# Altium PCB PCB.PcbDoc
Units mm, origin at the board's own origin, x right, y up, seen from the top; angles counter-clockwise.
Board outline 42.42 x 60.96 mm, 2 copper layers (Top Layer, Bottom Layer); 65 components, 46 nets, 264 pads, 71 vias.
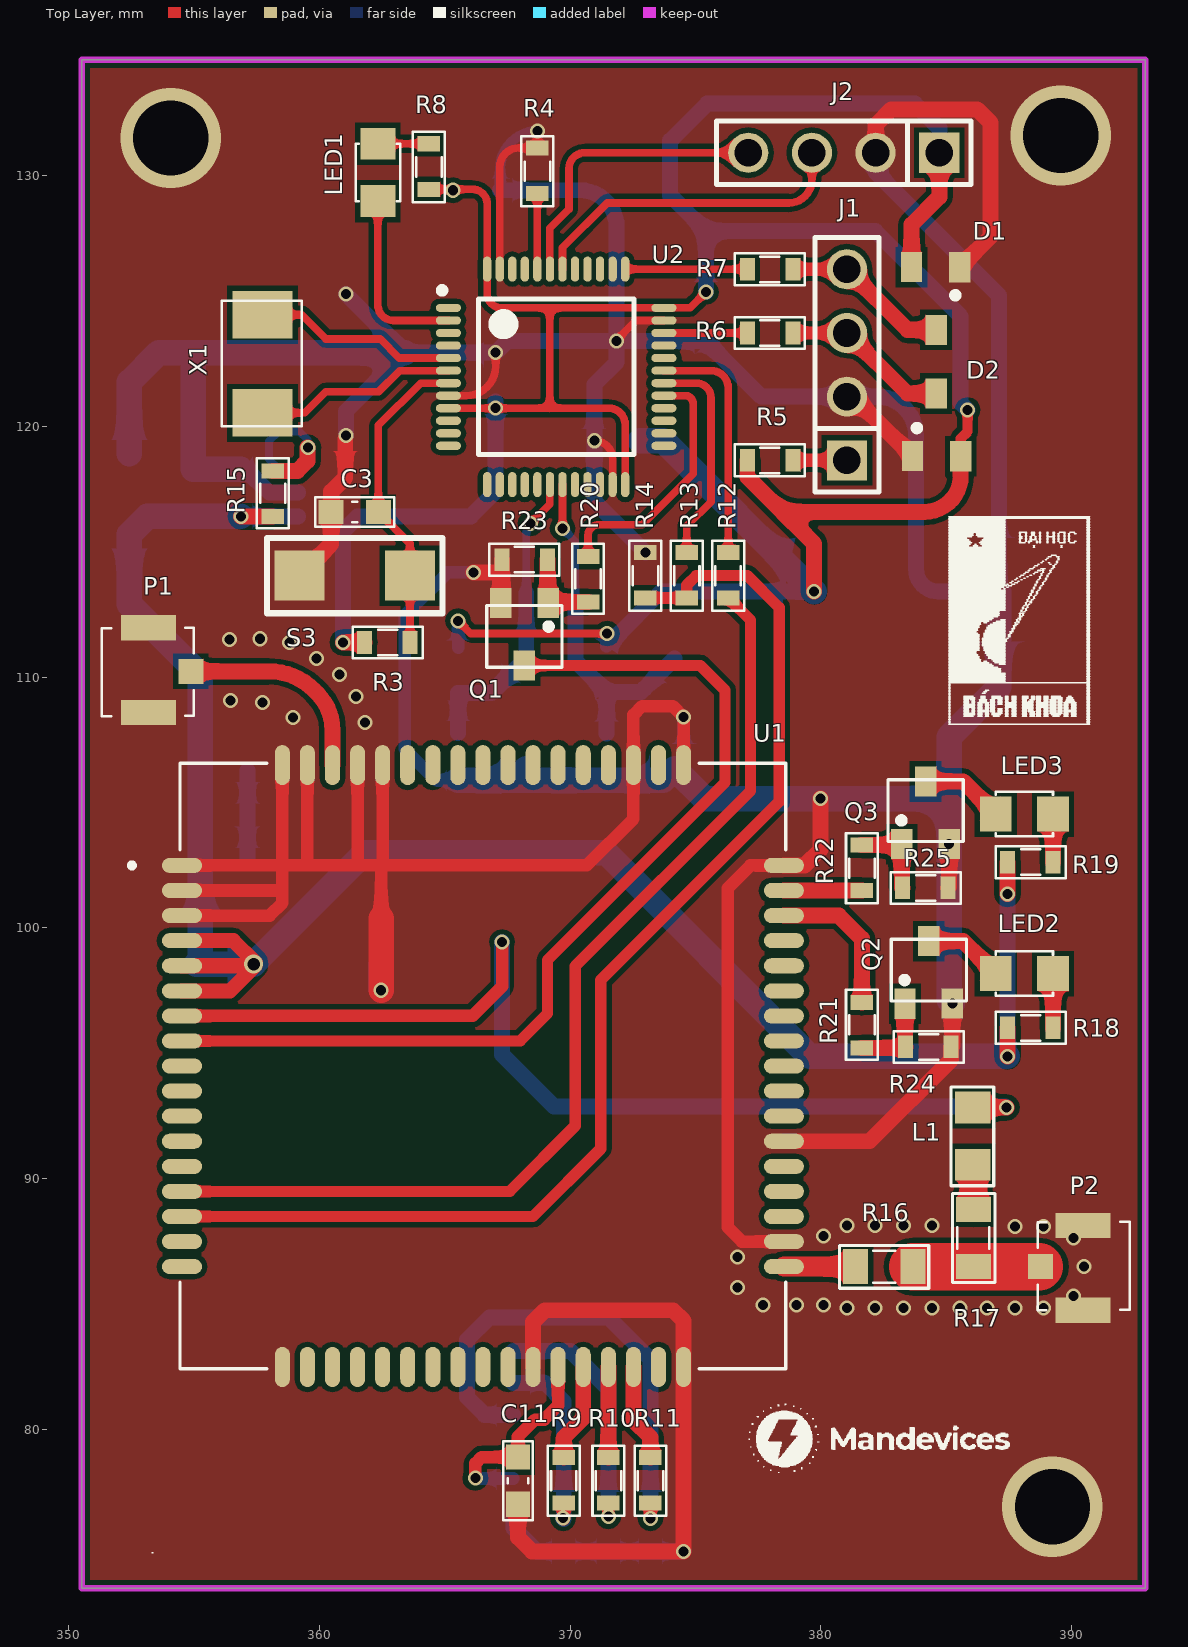
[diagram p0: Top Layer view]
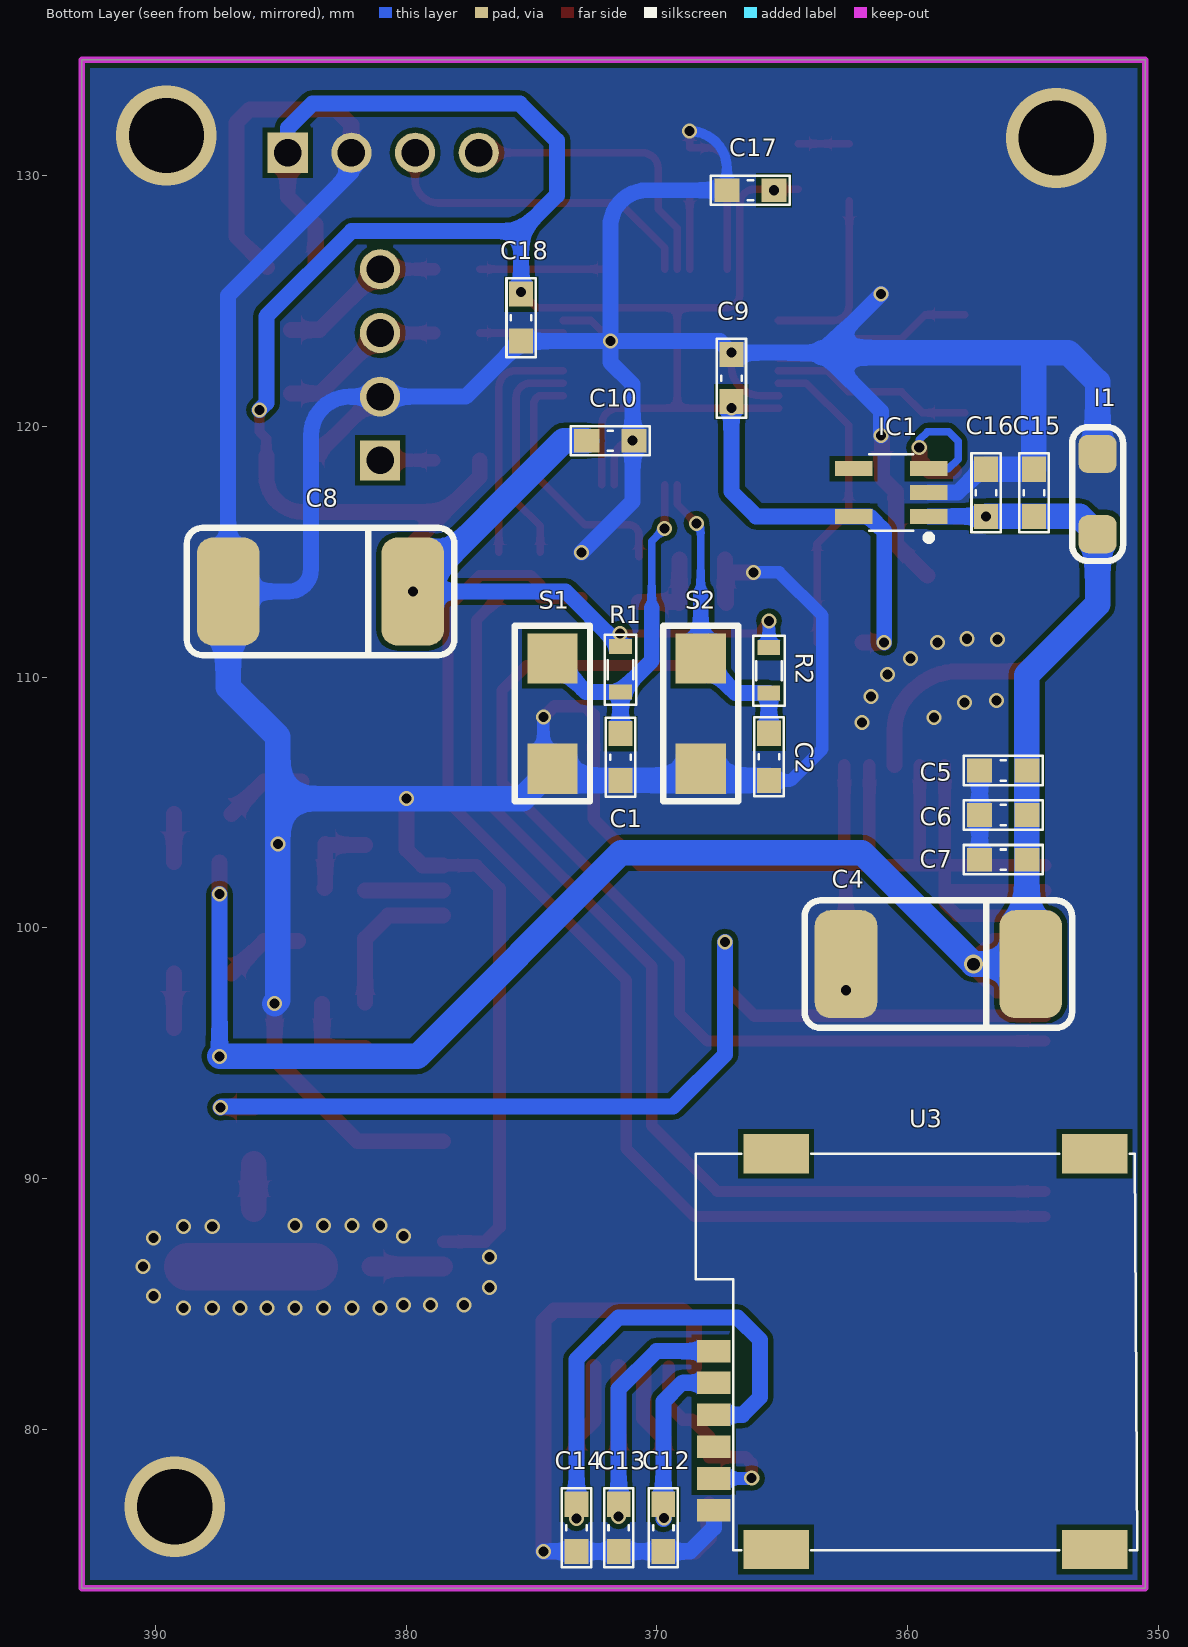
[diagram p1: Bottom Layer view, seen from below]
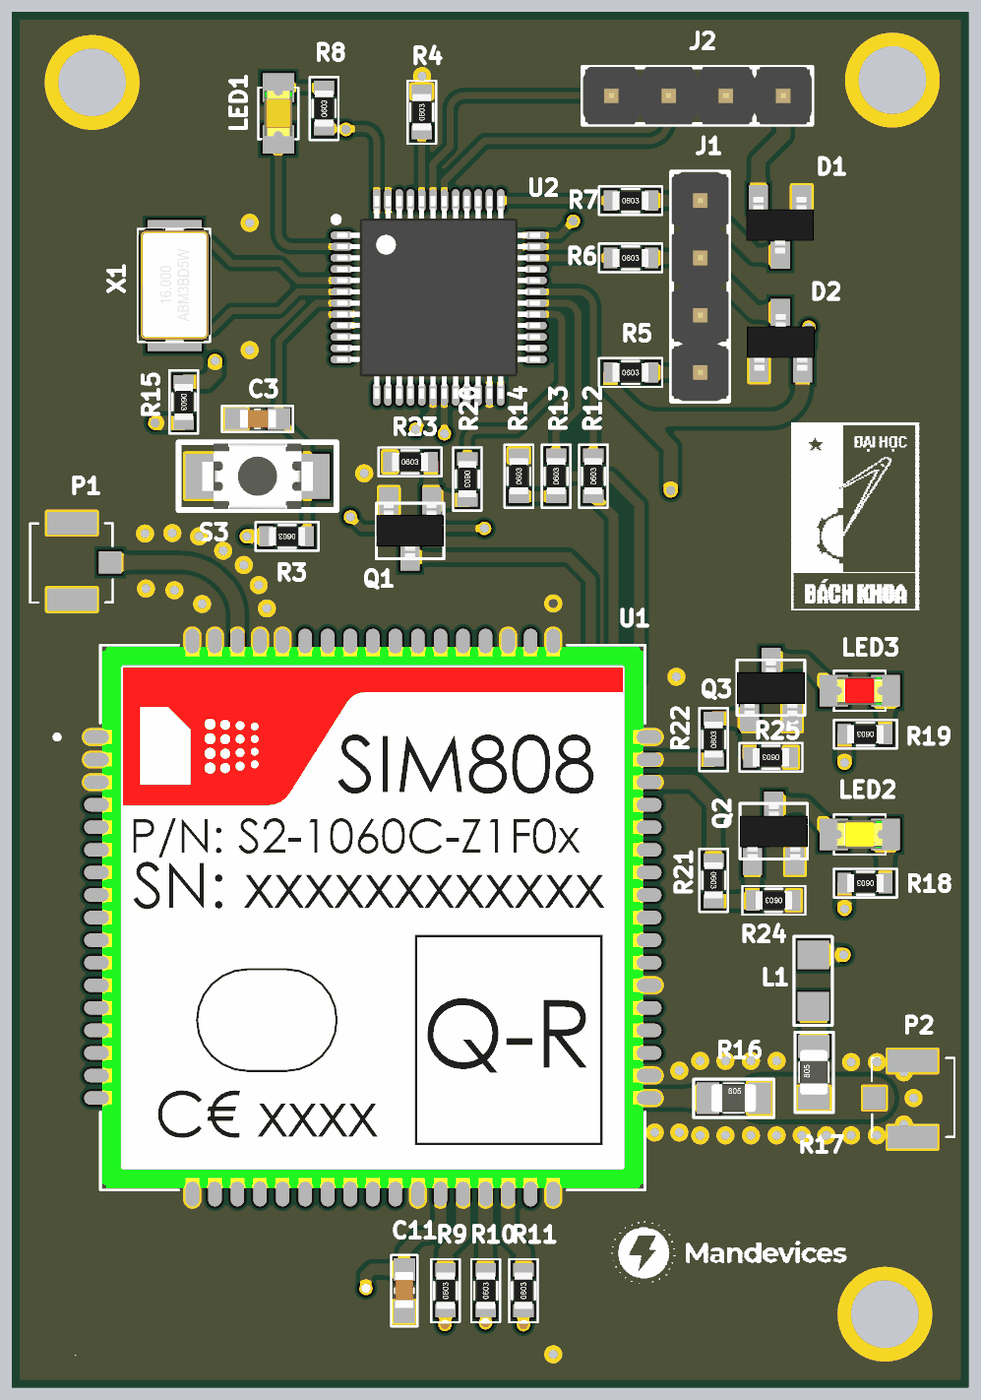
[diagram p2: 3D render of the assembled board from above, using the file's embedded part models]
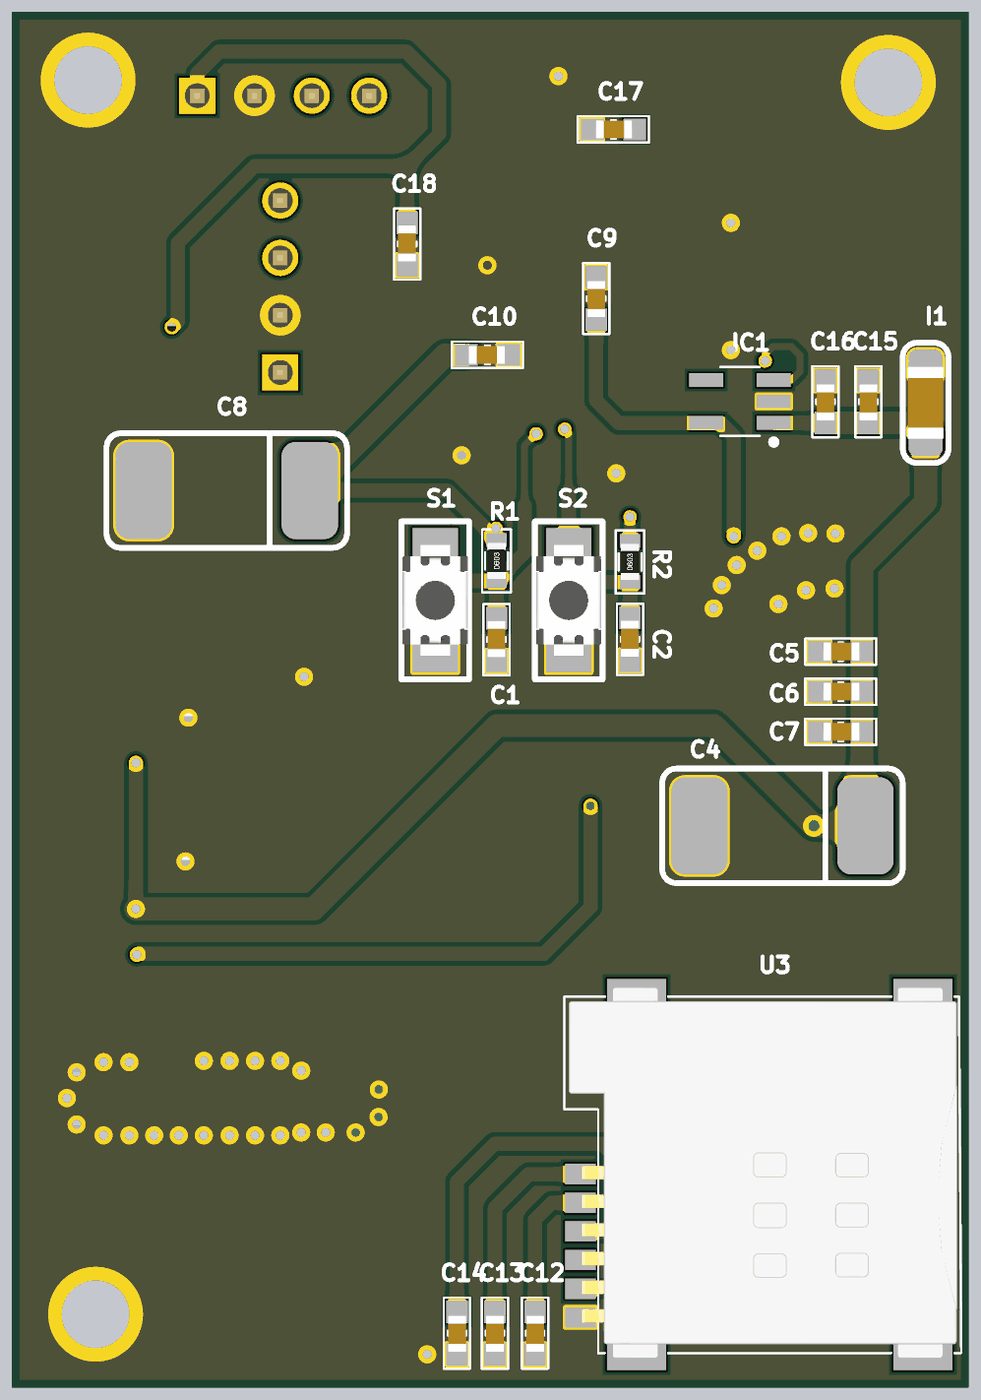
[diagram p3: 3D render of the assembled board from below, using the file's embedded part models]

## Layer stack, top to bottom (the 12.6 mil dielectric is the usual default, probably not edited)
Top Solder: solder mask 0.0102, Solder Resist, Dk 3.5
Top Layer: signal copper 0.0356
Dielectric 1: dielectric 0.32, FR-4, Dk 4.8
Bottom Layer: signal copper 0.0356
Bottom Solder: solder mask 0.0102, Solder Resist, Dk 3.5

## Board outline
350.52,73.66 392.938,73.66 392.938,134.62 350.52,134.62

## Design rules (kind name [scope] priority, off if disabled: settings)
Clearance [All] p1: gap=0.254 ignorepadtopadclearanceinfootprint=TRUE except(0.1: Arc-Arc Arc-Track Arc-SMDPad Track-Track Track-SMDPad SMDPad-SMDPad; 0.2: Arc-Fill Arc-Poly Arc-Region Track-Fill Track-Poly Track-Region SMDPad-Fill SMDPad-Poly SMDPad-Region THPad-Fill THPad-Poly THPad-Region Via-Fill Via-Poly Via-Region Fill-Fill Fill-Poly Fill-Region Poly-Poly Poly-Region Region-Region)
PolygonConnect [All] p1: connectstyle=Direct reliefconductorwidth=0.254 reliefentries=4 polygonreliefangle="90 Angle" airgapwidth=0.254
RoutingVias [All] p1: holewidth=0.4 width=0.6 viastyle="Through Hole" minholewidth=0.4 minwidth=0.6 maxholewidth=0.4 maxwidth=0.6
SolderMaskExpansion [All] p1: expansion=0.102
Width [All] p1: maxlimit=2.032 minlimit=0.305 preferedwidth=0.5
30 further rules are at their usual default settings.

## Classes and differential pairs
component class Sheet1: C3 C4 C5 C6 C7 C8 C9 C10 C11 C12 C13 C14 C15 C16 C17 C18 D1 D2 I1 IC1 J1 J2 L1 LED1 LED2 LED3 P1 P2 Q1 Q2 Q3 R3 R4 R5 R6 R7 R8 R9 R10 R11 R12 R13 R14 R15 R16 R17 R18 R19 R20 R21 R22 R23 R24 R25 S2 S3 U1 U2 U3 X1

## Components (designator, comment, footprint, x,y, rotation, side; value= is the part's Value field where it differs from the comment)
C1 "10uF" CAP_0603 371.45,106.807 r90 bottom value=33p
C2 "10uF" CAP_0603 365.531,106.82 r90 bottom value=33p
C3 "10uF" CAP_0603 361.411,116.586 r0 top value=33p
C4 "100uF" CAP_7343 358.902,98.552 r0 bottom
C5 "10uF" CAP_0603 356.188,106.274 r180 bottom value=33p
C6 "100nF" CAP_0603 356.188,104.496 r180 bottom value=33p
C7 "33pF" CAP_0603 356.188,102.718 r180 bottom value=33p
C8 "100uF" CAP_7343 383.54,113.411 r0 bottom
C9 "10uF" CAP_0603 367.03,121.92 r270 bottom value=33p
C10 "100nF" CAP_0603 371.856,119.424 r0 bottom value=33p
C11 "100nF" CAP_0603 367.919,77.953 r90 top value=33p
C12 "22pF" CAP_0603 369.744,76.073 r270 bottom value=33p
C13 "22pF" CAP_0603 371.522,76.073 r270 bottom value=33p
C14 "22pF" CAP_0603 373.204,76.073 r270 bottom value=33p
C15 "10uF" CAP_0603 354.965,117.348 r270 bottom value=33p
C16 "100nF" CAP_0603 356.87,117.348 r270 bottom value=33p
C17 "10uF" CAP_0603 366.268,129.413 r180 bottom value=33p
C18 "100nF" CAP_0603 375.412,124.333 r90 bottom value=33p
D1 "DIODE-BAV99" SOT23 384.599,125.097 r180 top
D2 "DIODE-BAV99" SOT23 384.589,120.057 r0 top
I1 "Batt" CAP_3216 352.425,117.297 r270 bottom value=33p
IC1 "RT9013" SOT23-5 360.656,117.358 r0 bottom
J1 "ST_LINK" JP4-D1T 381.038,118.641 r90 top
J2 "MPU" JP4-D1T 384.721,130.909 r180 top
L1 "47nH" L-0805 386.055,91.694 r270 top value="150 mH"
LED1 "LED" LED-0805-Orange 362.331,131.267 r270 top value="LED 3 ly Single Colour"
LED2 "LED" LED-0805-Yellow 389.255,98.171 r180 top value="LED 3 ly Single Colour"
LED3 "LED" LED-0805-Red 389.255,104.536 r180 top value="LED 3 ly Single Colour"
P1 "Antenna" IPXS 354.457,110.236 r0 top
P2 "Antenna" IPXS 389.179,86.479 r180 top
Q1 "2SC1815" SOT23D 368.173,111.709 r180 top value=C1815
Q2 "2SC1815" SOT23D 384.302,98.222 r0 top value=C1815
Q3 "2SC1815" SOT23D 384.175,104.587 r0 top value=C1815
R1 "10k" RES-SMD-0603 371.45,110.297 r90 bottom
R2 "10k" RES-SMD-0603 365.531,110.249 r90 bottom
R3 "10k" RES-SMD-0603 362.722,111.379 r180 top
R4 "100k" RES-SMD-0603 368.693,130.175 r90 top
R5 "10R" RES-SMD-0603 377.952,118.641 r0 top
R6 "10R" RES-SMD-0603 377.952,123.721 r0 top
R7 "10R" RES-SMD-0603 377.952,126.261 r0 top
R8 "1k" RES-SMD-0603 364.363,130.34 r90 top
R9 "22R" RES-SMD-0603 369.744,77.953 r90 top
R10 "22R" RES-SMD-0603 371.526,77.953 r90 top
R11 "22R" RES-SMD-0603 373.202,77.953 r90 top
R12 "1k" RES-SMD-0603 376.301,114.046 r90 top
R13 "1k" RES-SMD-0603 374.65,114.046 r90 top
R14 "4.7k" RES-SMD-0603 372.999,114.046 r90 top
R15 "100k" RES-SMD-0603 358.14,117.335 r270 top
R16 "0R" RES-SMD-0805 382.524,86.489 r0 top
R17 "10R" RES-SMD-0805 386.08,87.632 r90 top
R18 "1k" RES-SMD-0603 388.366,96.012 r180 top
R19 "1k" RES-SMD-0603 388.366,102.616 r180 top
R20 "4.7k" RES-SMD-0603 370.713,113.919 r270 top
R21 "4.7k" RES-SMD-0603 381.635,96.139 r270 top
R22 "4.7k" RES-SMD-0603 381.635,102.377 r90 top
R23 "47k" RES-SMD-0603 368.173,114.681 r0 top
R24 "47k" RES-SMD-0603 384.302,95.25 r180 top
R25 "47k" RES-SMD-0603 384.175,101.59 r180 top
S1 "SW-SMD" "SW 3x2x4" 374.167,108.544 r90 bottom
S2 "SW-SMD" "SW 3x2x4" 368.249,108.544 r90 bottom
S3 "SW-SMD" "SW 3x2x4" 361.411,114.046 r0 top
U1 "SIM808" XCVR_SIM808 366.522,94.488 r0 top
U2 "STM32" "LQFP 48" 369.443,121.971 r0 top
U3 "SIM-KF016" "Sim Socket" 360.045,83.185 r90 bottom value="Sim holder"
X1 "8Mhz" "XTAL 5032 SMD" 357.728,122.517 r90 top value=4Mhz

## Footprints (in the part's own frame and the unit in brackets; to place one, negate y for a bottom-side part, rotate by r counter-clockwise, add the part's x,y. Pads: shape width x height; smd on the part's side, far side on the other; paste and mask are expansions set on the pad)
CAP_0603 [mm]
  rect 1x0.95 smd mask+0.076: 1(-0.94,0) 2(0.94,0)
  silkscreen extent -1.57,-0.58 1.57,0.58, body extent -0.77,-0.39 0.83,0.41, height 0.9
CAP_3216 [mil]
  rrect50% 60x60 smd: 1(-62.99,0) 2(62.99,0)
  silkscreen extent -105,-40 105,40, body extent -63,-31 63,31, height 39
CAP_7343 [mm] "Capacitor Tantalum 7343"
  rrect50% 2.5x4.3 smd: 1(-3.81,0) 2(3.556,0)
  silkscreen extent -5.46,-2.54 5.21,2.54, body extent -3.81,-2.29 3.56,2.29, height 3
IPXS [mm] "SOT 23 _ 1-3-2"
  rect 1x1 smd: 1(0.415,-0.01)
  rect 2.2x1 smd: 2(-1.273,-1.658) 3(-1.278,1.73)
  silkscreen extent -3.13,-1.79 0.53,1.73, body extent -2.83,-1.49 0.31,1.56, height 1.55
JP4-D1T [mm] "4 pins, 1 row, straight, gold plating"
  rect 1.6x1.6 hole 1.1: 1(0,0)
  round 1.6 hole 1.1: 2(2.54,0) 3(5.08,0) 4(7.62,0)
  silkscreen extent -1.27,-1.27 8.89,1.27, body extent -1.27,-1.27 8.89,1.27, height 8.54
L-0805 [mil] "Compoment SMD 80x50mil"
  rect 50x55 smd: 1(-45,0) 2(45,0)
  silkscreen extent -77,-34 78,33, body extent -50,-20 50,20, height 43
LED-0805-Orange [mil]
  rect 50x55 smd: 1(0,0) 2(90,0)
  silkscreen extent 0,-35 90,35, body extent 5,-25 85,25, height 43
LED-0805-Red [mil]
  rect 50x55 smd: 1(0,0) 2(90,0)
  silkscreen extent 0,-35 90,35, body extent 5,-25 85,25, height 43
LED-0805-Yellow [mil]
  rect 50x55 smd: 1(0,0) 2(90,0)
  silkscreen extent 0,-35 90,35, body extent 5,-25 85,25, height 43
"LQFP 48" [mm] "LQFP, 48-Leads, Body 7,00x7,00mm, Pitch 0,50mm, IPC Medium Density"
  oval 1x0.33 smd: 1(-4.296,2.75) 2(-4.296,2.25) 3(-4.296,1.75) 4(-4.296,1.25) 5(-4.296,0.75) 6(-4.296,0.25) 7(-4.296,-0.25) 8(-4.296,-0.75) 9(-4.296,-1.25) 10(-4.296,-1.75) 11(-4.296,-2.25) 12(-4.296,-2.75) 25(4.296,-2.75) 26(4.296,-2.25) 27(4.296,-1.75) 28(4.296,-1.25) 29(4.296,-0.75) 30(4.296,-0.25) 31(4.296,0.25) 32(4.296,0.75) 33(4.296,1.25) 34(4.296,1.75) 35(4.296,2.25) 36(4.296,2.75)
  oval 0.33x1 smd: 13(-2.75,-4.296) 14(-2.25,-4.296) 15(-1.75,-4.296) 16(-1.25,-4.296) 17(-0.75,-4.296) 18(-0.25,-4.296) 19(0.25,-4.296) 20(0.75,-4.296) 21(1.25,-4.296) 22(1.75,-4.296) 23(2.25,-4.296) 24(2.75,-4.296) 37(2.75,4.296) 38(2.25,4.296) 39(1.75,4.296) 40(1.25,4.296) 41(0.75,4.296) 42(0.25,4.296) 43(-0.25,4.296) 44(-0.75,4.296) 45(-1.25,4.296) 46(-1.75,4.296) 47(-2.25,4.296) 48(-2.75,4.296)
  silkscreen extent -4.67,-3.1 3.1,3.57, body extent -4.5,-4.5 4.5,4.5, height 1.6
RES-SMD-0603 [mm]
  rect 0.6x0.9 smd: 1(-0.889,0) 2(0.927,0)
  silkscreen extent -1.4,-0.64 1.4,0.64, body extent -0.8,-0.4 0.8,0.4, height 0.43
RES-SMD-0805 [mil]
  rect 39.37x55 smd: 1(-45,0) 2(45,0)
  silkscreen extent -70,-34 70,33, body extent -39,-25 39,25, height 31
"Sim Socket" [mm] "Socket Micro Sim 6P Push"
  rect 0.9x1.35 smd: 1(-5.145,7.685) 2(-2.605,7.685) 3(-0.065,7.685) 5(-6.415,7.685) 6(-3.875,7.685) 7(-1.335,7.685)
  rect 1.56x2.61 smd: ""(-7.975,-7.5) ""(-7.975,5.2) ""(7.805,-7.5) ""(7.805,5.2)
  silkscreen extent -8,-9.2 7.8,8.4, body extent -8.2,-9 8.2,8.2, height 1.35
SOT23 [mm] "SOT 23 _ 1-3-2"
  rect 0.85x1.2 smd: 1(-0.94,-1.245) 2(0.985,-1.25) 3(0.005,1.25)
  silkscreen extent -0.89,-0.25 -0.64,0, body extent -1.47,-1.33 1.53,1.17, height 1.06
SOT23-5 [mm] "SOT23, 5-Leads, Body 3.0x3.0mm (max), Pitch 0.95mm, IPC Medium Density"
  rect 1.5x0.6 smd: 1(-1.5,0.95) 2(-1.5,0) 3(-1.5,-0.95) 4(1.5,-0.95) 5(1.5,0.95)
  silkscreen extent -1.62,-1.52 0.87,1.92, body extent -1.75,-1.52 1.75,1.53, height 1.45
SOT23D [mm] "SOT 23C - 1-3-2 - BCE"
  rect 0.85x1.2 smd: 1(-0.95,-1.25) 2(0.94,-1.245) 3(0,1.25)
  silkscreen extent -1.5,-1.14 1.5,1.32, body extent -1.5,-1.17 1.5,1.33, height 1.06
"SW 3x2x4" [mm]
  rect 2x2 smd: 1(-2.2,0) 2(2.2,0)
  silkscreen extent -3.5,-1.5 3.5,1.5, body extent -2.45,-1.45 2.45,1.45, height 2
XCVR_SIM808 [mm]
  oval 1.6x0.6 smd: 1(-12,8) 2(-12,7) 3(-12,6) 4(-12,5) 5(-12,4) 6(-12,3) 7(-12,2) 8(-12,1) 9(-12,0) 10(-12,-1) 11(-12,-2) 12(-12,-3) 13(-12,-4) 14(-12,-5) 15(-12,-6) 16(-12,-7) 17(-12,-8) 35(12,-8) 36(12,-7) 37(12,-6) 38(12,-5) 39(12,-4) 40(12,-3) 41(12,-2) 42(12,-1) 43(12,0) 44(12,1) 45(12,2) 46(12,3) 47(12,4) 48(12,5) 49(12,6) 50(12,7) 51(12,8)
  oval 0.6x1.6 smd: 18(-8,-12) 19(-7,-12) 20(-6,-12) 21(-5,-12) 22(-4,-12) 23(-3,-12) 24(-2,-12) 25(-1,-12) 26(0,-12) 27(1,-12) 28(2,-12) 29(3,-12) 30(4,-12) 31(5,-12) 32(6,-12) 33(7,-12) 34(8,-12) 52(8,12) 53(7,12) 54(6,12) 55(5,12) 56(4,12) 57(3,12) 58(2,12) 59(1,12) 60(0,12) 61(-1,12) 62(-2,12) 63(-3,12) 64(-4,12) 65(-5,12) 66(-6,12) 67(-7,12) 68(-8,12)
  silkscreen extent -14.1,-12.07 12.07,12.07, body extent -12,-12 12,12, height 2.8
"XTAL 5032 SMD" [mm] "SMD 5032 XTAL Footprint"
  rect 1.9x2.4 smd: 1(-1.981,0) 2(1.93,0)
  silkscreen extent -2.51,-1.57 2.49,1.63, body extent -2.5,-1.6 2.5,1.6, height 1.31

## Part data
C1 C2 C3 C5 C6 C7 C9 C10 C11 C12 C13 C14 C15 C16 C17 C18: library part CapSMD, "Capacitor"
C4 C8: library part "Cap Pol", "Tantalum"
D1 D2: "ZENER, SOT23,", Current - Average Rectified (Io) (per Diode)=200mA, Current - Reverse Leakage @ Vr="2.5礎 @ 70V", Manufacturer="ON Semiconductor / Fairchild", Manufacturer Part Number=BAV99, Package / Case="TO-236-3, SC-59, SOT-23-3", Standard Package=1, Supplier Device Package="SOT-23-3 (TO-236)", Supplier Part Number 1=BAV99FSCT-ND, Voltage - DC Reverse (Vr) (Max)=70V, Voltage - Forward (Vf) (Max) @ If="1.25V @ 150mA"
I1: library part CapSMD, "Pad"
IC1: "RT9013-33GB IC REG LINEAR 3.3V 500mA SOT23-5"
J1 J2: library part Header4, "Header IDC, 4 x 1 Pin Vertical 2.54mm Pitch (Non-Boxed, Male)", Manufacturer="Würth Elektronik eiSos GmbH", partNo=613002143121
L1: library part "Inductor Ferit", "Inductor"
LED1 LED2 LED3: "LED Single colour Green and Red"
P1 P2: library part IPXSx66, "Antenna GSM GPS"
Q1 Q2 Q3: "NPN 600mW, ECB"
R1 R2 R3 R4 R5 R6 R7 R8 R9 R10 R11 R12 R13 R14 R15 R16 R17 R18 R19 R20 R21 R22 R23 R24 R25: library part "Resistor - SMD", "Resistor", Manufacturer="Generic Components"
S1 S2 S3: "Switch"
U1: "SIM808 GPS, GPRS/GSM RF Arduino Platform Evaluation Expansion Board", Package=None
U2: library part STM32F103C8T6, "STM32 ARM-based 32-bit MCU with 64 Kbytes Flash, 64-pin LQFP, Industrial Temperature"
U3: library part "Sim holder", "SIM Card Holder KF-016"
X1: library part XT2, "Crystal For all Crystal 2pin."

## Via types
v1: diameter 0.6, hole 0.4, Top Layer to Bottom Layer, 67 vias
v2: diameter 4, hole 3, Top Layer to Bottom Layer, 3 vias
v3: diameter 0.762, hole 0.508, Top Layer to Bottom Layer, 1 vias

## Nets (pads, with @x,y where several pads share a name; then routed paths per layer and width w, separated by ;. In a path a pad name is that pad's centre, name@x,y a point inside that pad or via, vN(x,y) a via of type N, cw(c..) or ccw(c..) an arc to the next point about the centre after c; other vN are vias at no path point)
3V3: C8.1 C9.2 C10.2 C17.2 C18.2 D1.2 D2.2 IC1.5 J2.1 R1.2 R2.2 R3.2 R5.1 R8.1 U2.9 U2.24 U2.36 U2.48 | length 127.8
  Top Layer w0.305: R8.1 366.103,129.451 cw(c366.103,128.861) 366.693,128.861 U2.48 366.693,125.293 ccw(c367.265,125.293) 367.265,124.721 369.189,124.721 ; U2.9 v1(367.03,120.721) 369.189,120.721 ; v1(365.531,112.243) 366.039,111.735 v1(371.475,111.735) ; U2.24 372.193,120.072 ccw(c371.544,120.072) 371.544,120.721 369.189,120.721 ; v1(375.412,125.349) 374.784,124.721 U2.36 369.189,124.721 ; 369.189,120.721 369.189,124.721
  Top Layer w0.4: D2.2 385.574,119.509 385.851,119.786 v1(385.851,120.65)
  Top Layer w0.635: v1(360.934,111.379) R3.2 ; R5.1 377.063,117.983 378.46,116.586 ; v1(379.73,113.411) 379.73,115.316 378.46,116.586 ; D1.2 383.613,128.039 384.721,129.146 J2.1 ; D2.2 385.574,118.03 cw(c384.13,118.03) 384.13,116.586 378.46,116.586
  Bottom Layer w0.5: R2.2 v1(365.531,112.243) ; R1.2 371.45,111.709 v1(371.475,111.735)
  Bottom Layer w0.635: v1(360.934,111.379) 360.934,115.824 361.518,116.408 IC1.5 366.039,116.408 367.03,117.399 v1(367.03,120.721) C9.2 ; R1.2@371.718,111.492 373.637,113.411 v1(379.73,113.411) ; v1(375.412,125.349) 375.412,127.787 ; J2.1 384.721,131.89 383.743,132.867 375.463,132.867 373.99,131.394 373.99,129.21 375.412,127.787 ; v1(385.851,120.65) 385.574,120.927 385.574,124.386 382.173,127.787 375.412,127.787
  Bottom Layer w1.016: C10.2 373.717,119.424 v1(379.73,113.411)
  other v1: 365.328,129.413
Button1: C2.2 R2.1 S2.2 U2.18 | length 12.2
  Top Layer w0.305: v1(368.427,116.129) 369.193,116.895 U2.18
  Bottom Layer w0.305: 368.249,113.36 368.249,115.951 v1(368.427,116.129)
  Bottom Layer w0.635: C2.2 R2.1 366.865,109.36 S2.2 368.249,113.36
Button2: C1.2 R1.1 S1.2 U2.19 | length 13.9
  Top Layer w0.305: U2.19 369.693,115.93 v1(369.697,115.926)
  Bottom Layer w0.305: v1(369.697,115.926) 370.205,115.418 370.205,112.751
  Bottom Layer w0.635: 370.205,112.751 370.205,110.652 R1.1 ; C1.2 R1.1 ; S1.2 372.831,109.408 R1.1
GND: C1.1 C2.1 C3.1 C4.2 C5.1 C6.1 C7.1 C8.2 C9.1 C10.1 C11.1 C12.2 C13.2 C14.2 C15.1 C16.1 C17.1 C18.1 D1.1 D2.1 I1.1 IC1.2 J1.2 J2.2 P1.2 P1.3 P2.2 P2.3 Q1.2 Q2.2 Q3.2 R4.2 R14.2 R23.1 R24.1 R25.1 S1.1 S2.1 S3.1 U1.1 U1.2 U1.3 U1.18 U1.28 U1.34 U1.36 U1.40 U1.51 U1.52 U1.54 U1.64 U1.65 U1.67 U1.68 U2.8 U2.23 U2.35 U2.47 U3.5 | length 327.8
  Top Layer w0.305: U2.8 365.853,121.221 ccw(c365.853,122.398) 367.03,122.398 v1(367.03,122.936) ; U2.47 367.193,130.338 cw(c367.957,130.338) 367.957,131.102 R4.2 368.693,131.775 v1(368.706,131.775) ; v1(370.967,119.424) cw(c370.967,118.698) 371.693,118.698 U2.23 ; v1(371.856,123.393) 371.856,123.444 372.633,124.221 U2.35
  Top Layer w0.5: U1.3 358.019,100.488 358.522,100.991 358.522,101.549 ; U1.2 358.461,101.488 358.522,101.549 ; U1.1 358.472,102.488 ; U1.68 358.522,102.538 358.472,102.488 ; U1.67 359.522,102.524 359.486,102.488 ; U1.65 361.522,102.517 361.493,102.488 ; 362.458,100.381 362.458,102.462 362.484,102.488 ; U1.64 362.522,102.526 ; U1.52 v1(374.522,108.408) 374.091,108.839 372.872,108.839 372.522,108.489 U1.54 372.522,104.349 370.661,102.488 362.56,102.488 362.522,102.526 ; U1.36 376.849,87.488 376.276,88.062 376.276,101.575 377.189,102.488 U1.51 ; 358.472,102.488 359.486,102.488 ; 358.472,102.488 358.522,102.438 358.522,101.549 ; 359.486,102.488 361.493,102.488 ; 361.493,102.488 362.484,102.488 ; 362.484,102.488 362.522,102.526
  Top Layer w0.635: S3.1 360.471,115.306 C3.1 360.471,117.393 361.03,117.952 v1@361.03,119.495 ; v1(366.141,114.173) 367.233,114.173 Q1.2 367.284,113.005 R23.1 ; C11.1 367.919,75.692 368.478,75.133 v1(374.523,75.133) 374.523,82.487 U1.34 374.522,84.328 374.101,84.749 368.987,84.749 368.522,84.284 U1.28 ; U1.40 381.937,91.488 385.191,94.742 R24.1 385.242,95.301 v1(385.242,96.977) ; U1.51 379.348,102.488 379.984,103.124 v1(379.984,105.156) ; J1.2 381.28,121.181 D2.1 ; J2.2 382.181,132.016 382.803,132.639 386.232,132.639 386.766,132.105 386.766,127.568 D1.1 ; R25.1 385.115,101.64 v1(385.115,103.342)
  Top Layer w1.016: v1(362.458,97.511) 362.458,100.381
  Bottom Layer w0.4: C17.1 367.208,130.277 cw(c368.706,130.277) v1(368.706,131.775)
  Bottom Layer w0.5: C2.1 364.655,105.88 363.398,107.137 363.398,112.446 365.125,114.173 v1(366.141,114.173) ; S1.1 374.522,106.699 v1(374.522,108.408)
  Bottom Layer w0.635: C16.1 357.073,118.288 358.003,117.358 IC1.2 ; C7.1 C6.1 C5.1 ; v1(361.061,119.634) 361.061,120.599 363.398,122.936 ; v1(361.061,125.273) 363.398,122.936 ; C17.1 370.382,129.413 cw(c370.382,127.939) 371.856,127.939 v1(371.856,123.393) ; U3.5 367.73,76.072 368.668,75.133 C12.2 C13.2 C14.2 v1(374.523,75.133) ; v1(372.999,114.973) 370.967,117.005 v1(370.967,119.424) 370.967,121.666 371.856,122.555 v1(371.856,123.393) ; J2.2 382.181,130.137 387.096,125.222 C8.2 384.683,113.411 cw(c384.683,114.3) 383.794,114.3 383.794,119.634 ccw(c382.247,119.634) 382.247,121.181 J1.2 377.624,121.181 C18.1 v1(371.856,123.393) ; 363.398,122.936 v1(367.03,122.936) 367.487,123.393 v1(371.856,123.393)
  Bottom Layer w1.016: I1.1 352.425,121.768 353.593,122.936 355.067,122.936 ; C16.1 C15.1 354.965,122.834 cw(c355.067,122.834) 355.067,122.936 ; v1(362.458,97.511) C4.2 ; 363.398,122.936 355.067,122.936 ; C2.1 S2.1@367.785,105.88 ; S2.1 S2.1@367.785,105.88 ; v1(385.242,96.977) 385.115,97.104 v1(385.115,103.342) 385.115,105.156 ; C8.2 387.096,109.601 385.115,107.62 385.115,105.156 ; S2.1@367.785,105.88 373.704,105.88 S1.1 375.355,105.156 v1(379.984,105.156) 385.115,105.156
  other v1: 381.038,84.836 382.157,84.836 383.286,84.836 384.429,84.836 385.539,84.836 386.631,84.836 387.731,84.836 388.874,84.836 377.698,84.963 379.022,84.963 380.111,84.963 390.068,85.319 376.682,85.65 390.5,86.488 376.668,86.868 390.068,87.63 380.111,87.702 387.731,88.081 388.874,88.081 381.038,88.137 382.157,88.137 383.286,88.138 384.429,88.137 361.823,108.185 358.953,108.382 357.728,108.991 356.464,109.068 361.463,109.22 360.803,110.109 359.889,110.744 358.816,111.379 356.422,111.506 357.632,111.528
  other v2: 389.23,76.911 354.076,131.496 389.56,131.597
GPIO_PWRKEY: R20.1 U2.29 | length 10.3
  Top Layer w0.305: R20.1 370.713,115.646 cw(c371.145,115.646) 371.145,116.078 372.872,116.078 374.904,118.11 374.904,120.904 ccw(c374.587,120.904) 374.587,121.221 U2.29
GPS: R16.1 U1.35 | length 2.9
  Top Layer w0.7: R16.1@381.38,86.488 R16.1
  Top Layer w0.8: U1.35 R16.1@381.38,86.488
GSM: P1.1 U1.66 | length 8.3
  Top Layer w0.635: P1.1 357.987,110.226 cw(c357.987,107.686) 359.783,109.482 359.918,109.347 cw(c358.46,107.889) 360.522,107.889 U1.66
NetD1_3: D1.3 J1.4 R7.2 | length 6.7
  Top Layer w0.508: R7.2 J1.4
  Top Layer w0.635: J1.4 383.452,123.847 D1.3
NetD2_3: D2.3 J1.3 R6.2 | length 6.7
  Top Layer w0.508: R6.2 J1.3
  Top Layer w0.635: J1.3 383.452,121.307 D2.3
NetIC1_3: IC1.3 R15.1 | length 6.3
  Top Layer w0.635: R15.1 359.128,118.224 359.522,118.618 359.522,119.151 v1(359.537,119.151)
  Bottom Layer w0.305: IC1.3 358.374,118.308 357.988,118.694 357.988,119.405 358.369,119.786 359.207,119.786 359.537,119.456 v1(359.537,119.151)
NetJ1_1: J1.1 R5.2 | length 2.2
  Top Layer w0.508: R5.2 J1.1
NetL1_2: L1.2 R17.2 | length 1.8
  Top Layer w1.016: R17.2 L1.2@386.08,90.594
NetLED1_1: LED1.1 R8.2 | length 2
  Top Layer w0.305: LED1.1 R8.2
NetLED1_2: LED1.2 U2.2 | length 7.3
  Top Layer w0.305: LED1.2 362.331,124.841 ccw(c362.951,124.841) 362.951,124.221 U2.2
NetLED2_1: LED2.1 R18.1 | length 2.2
  Top Layer w0.635: R18.1 LED2.1
NetLED2_2: LED2.2 Q2.3 | length 3.2
  Top Layer w0.635: Q2.3 385.668,99.472 LED2.2
NetLED3_1: LED3.1 R19.1 | length 1.9
  Top Layer w0.635: R19.1 LED3.1
NetLED3_2: LED3.2 Q3.3 | length 3.3
  Top Layer w0.635: Q3.3 385.668,105.837 LED3.2
NETLIGHT: R22.1 U1.50 | length 3.1
  Top Layer w0.635: U1.50 R22.1
NetP2_1: P2.1 R16.2 R17.1 | length 5
  Top Layer w1.9: R16.2 R17.1 P2.1@388.713,86.489
NetQ1_1: Q1.1 R20.2 R23.2 | length 3.3
  Top Layer w0.635: R23.2 369.1,112.982 Q1.1 369.156,112.992 R20.2
NetQ2_1: Q2.1 R21.2 R24.2 | length 3.5
  Top Layer w0.635: R21.2 383.338,95.212 R24.2 383.352,95.273 Q2.1
NetQ3_1: Q3.1 R22.2 R25.2 | length 3.4
  Top Layer w0.635: R22.2 383.192,103.304 Q3.1 383.225,101.613 R25.2
NetR4_1: R4.1 U2.44 | length 3
  Top Layer w0.305: U2.44 R4.1
NetR9_2: R9.2 U1.30 | length 3.9
  Top Layer w0.635: R9.2@369.744,78.867 369.744,79.676 370.522,80.454 U1.30
NetR10_2: R10.2 U1.31 | length 3.6
  Top Layer w0.635: R10.2@371.522,78.867 U1.31
NetR11_2: R11.2 U1.32 | length 3.9
  Top Layer w0.635: U1.32 372.522,80.36 373.204,79.678 R11.2@373.204,78.867
NetU2_5: U2.5 X1.2 | length 8.1
  Top Layer w0.305: X1.2 359.295,124.448 360.26,123.483 361.03,123.483 362.419,123.483 363.181,122.721 U2.5
NetU2_6: U2.6 X1.1 | length 8.1
  Top Layer w0.305: X1.1 359.408,120.536 360.246,121.374 361.03,121.374 362.357,121.374 363.204,122.221 U2.6
NRST: C3.2 R3.1 S3.2 U2.7 | length 12.7
  Top Layer w0.305: R3.1 S3.2 363.611,115.326 C3.2 362.351,120.035 364.037,121.721 U2.7
RX1: R12.2 U2.31 | length 9.5
  Top Layer w0.305: U2.31 375.619,122.221 cw(c375.619,121.539) 376.301,121.539 R12.2
SCL: J2.3 U2.42 | length 13.1
  Top Layer w0.305: U2.42 369.693,127.123 371.475,128.905 378.714,128.905 ccw(c378.714,129.832) 379.641,129.832 J2.3
SDA: J2.4 U2.43 | length 11.8
  Top Layer w0.305: U2.43 369.193,127.893 369.951,128.651 369.951,130.274 cw(c370.586,130.274) 370.586,130.909 J2.4
SIM_CLK: C13.1 R10.1 U3.3 | length 9.6
  Top Layer w0.5: v1(371.522,76.53) 371.526,76.534 R10.1
  Bottom Layer w0.635: U3.3 370.016,83.12 371.522,81.614 C13.1
SIM_DATA: C12.1 R9.1 U3.7 | length 7.7
  Top Layer w0.4: v1@369.744,76.425 369.721,76.448 v1(369.721,76.456) 369.721,76.43 v1@369.748,76.403
  Top Layer w0.5: v1@369.744,76.425 R9.1
  Bottom Layer w0.635: U3.7 369,81.85 369.744,81.106 C12.1@369.744,77.051 ; v1(369.721,76.456) 369.744,76.432 C12.1
SIM_PWRKEY: Q1.3 U1.8 | length 39.3
  Top Layer w0.45: U1.8 368.005,95.488 369.1,96.583 369.1,98.717 376.174,105.791 376.174,109.474 375.189,110.459 Q1.3
SIM_RST: C14.1 R11.1 U3.2 | length 19.1
  Top Layer w0.5: v1(373.202,76.45) R11.1
  Bottom Layer w0.635: U3.2 366.587,80.58 365.887,81.28 365.887,83.566 366.776,84.455 371.537,84.455 373.204,82.788 C14.1@373.204,77.051
SIM_RX: R13.1 R14.1 U1.15 | length 48.9
  Top Layer w0.45: U1.15 368.521,88.488 371.221,91.188 371.221,97.917 378.333,105.029 378.333,112.776 377.063,114.046 375.031,114.046 374.65,113.665 R13.1 R14.1
SIM_TX: R12.1 U1.14 | length 41.1
  Top Layer w0.45: U1.14 367.587,89.488 370.205,92.106 370.205,98.472 377.19,105.457 377.19,112.268 R12.1
SIM_VCC: C11.2 U1.29 U3.1 | length 8.4
  Top Layer w0.5: v1(366.217,78.054) 366.217,78.638 366.471,78.892 C11.2 367.919,79.705 368.605,80.391 368.96,80.391 369.522,80.953 U1.29
  Bottom Layer w0.5: v1(366.217,78.054) 366.231,78.04 U3.1
STATUS: R21.1 U1.49 | length 6
  Top Layer w0.635: U1.49 380.715,100.488 381.635,99.568 R21.1
SWCLK: R7.1 U2.37 | length 4.9
  Top Layer w0.305: U2.37 377.057,126.267 R7.1
SWDIO: R6.1 U2.34 | length 3.3
  Top Layer w0.305: U2.34 R6.1
TX1: R13.2 U2.30 | length 8.8
  Top Layer w0.305: U2.30 375.031,121.721 cw(c375.031,121.133) 375.619,121.133 375.619,116.996 374.65,116.027 R13.2
VBAT: C4.1 C5.2 C6.2 C7.2 C15.2 C16.2 I1.2 IC1.1 R15.2 R18.2 R19.2 U1.4 U1.5 U1.6 | length 82.6
  Top Layer w0.6: U1.6 356.441,97.488 v3@357.441,98.488 ; U1.5 v3@357.378,98.488 ; U1.4 356.569,99.488 v3@357.441,98.615
  Top Layer w0.635: v1(356.87,116.408) R15.2 ; v1(387.439,94.869) R18.2 ; v1(387.439,101.346) R19.2
  Bottom Layer w0.635: v1(356.87,116.408) IC1.1 ; v1(387.439,94.869) v1(387.439,101.346)
  Bottom Layer w1.016: v1(356.87,116.408) C15.2 353.136,116.408 I1.2 352.425,112.903 355.248,110.08 355.248,106.045 355.248,104.267 355.248,102.489 355.248,98.708 C4.1 v3(357.378,98.552) 361.823,102.997 371.424,102.997 379.552,94.869 v1(387.439,94.869)
VDD_EXT: L1.1 U1.7 | length 41.9
  Top Layer w0.5: U1.7 366.109,96.488 367.284,97.663 v1(367.284,99.441)
  Top Layer w0.635: L1.1 v1(387.401,92.837)
  Bottom Layer w0.635: v1(367.284,99.441) 367.284,94.945 369.349,92.88 387.358,92.88 v1(387.401,92.837)
pads on no net: IC1.4 U1.9 U1.10 U1.11 U1.12 U1.13 U1.16 U1.17 U1.19 U1.20 U1.21 U1.22 U1.23 U1.24 U1.25 U1.26 U1.27 U1.33 U1.37 U1.38 U1.39 U1.41 U1.42 U1.43 U1.44 U1.45 U1.46 U1.47 U1.48 U1.53 U1.55 U1.56 U1.57 U1.58 U1.59 U1.60 U1.61 U1.62 U1.63 U2.1 U2.3 U2.4 U2.10 U2.11 U2.12 U2.13 U2.14 U2.15 U2.16 U2.17 U2.20 U2.21 U2.22 U2.25 U2.26 U2.27 U2.28 U2.32 U2.33 U2.38 U2.39 U2.40 U2.41 U2.45 U2.46 U3. U3.6

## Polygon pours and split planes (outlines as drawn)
GND on Bottom Layer "GND_L02_P002" (solid, remove dead copper, pour order 2): 350.52,73.66 392.938,73.66 392.938,134.62 350.52,134.62
GND on Top Layer "GND_L01_P000" (solid, remove dead copper, pour order 0): 350.52,73.66 392.938,73.66 392.938,134.62 350.52,134.62

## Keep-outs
Keep-Out Layer:
  lines w0.254: 350.52,73.66 392.938,73.66 392.938,134.62 387.35,134.62 350.52,134.62 350.52,73.66

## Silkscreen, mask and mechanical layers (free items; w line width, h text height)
Top Overlay:
  drawing of 1343 lines, arcs and shapes, not listed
